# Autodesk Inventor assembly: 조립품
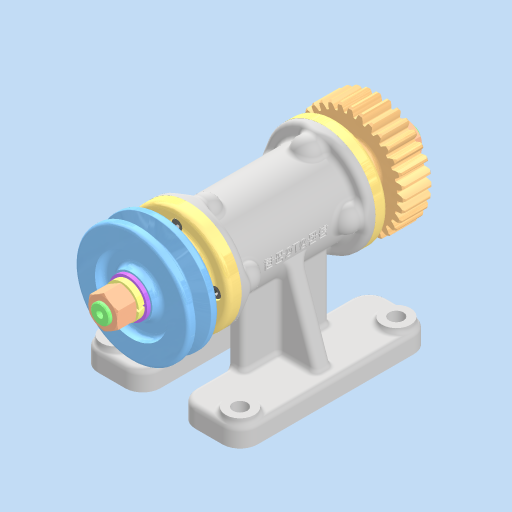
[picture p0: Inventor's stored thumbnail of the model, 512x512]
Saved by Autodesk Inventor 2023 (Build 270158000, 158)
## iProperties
Created: 2026-06
Part Number: 조립품
Document SubType Name: Assembly
Designer: home
Author: home
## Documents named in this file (18)
- C:\Users\home\Desktop\760603V1009\조립품.iam
- C:\Users\home\Desktop\760603V1009\부품.ipt
- C:\Users\home\Desktop\760603V1009\커버.ipt
- C:\Users\home\Desktop\760603V1009\6각 구멍붙이 볼트 M4x8.ipt
- C:\Users\home\Desktop\760603V1009\부품_MIR.ipt
- C:\Users\home\Desktop\760603V1009\커버_MIR.ipt
- C:\Users\home\Desktop\760603V1009\6각 구멍붙이 볼트 M4x8_MIR.ipt
- C:\Users\home\Desktop\760603V1009\깊은 홈 볼 베어링 6904.ipt
- C:\Users\home\Desktop\760603V1009\깊은 홈 볼 베어링 6904_MIR.ipt
- C:\Users\home\Desktop\760603V1009\축.ipt
- C:\Users\home\Desktop\760603V1009\오일 실 20 35 8.ipt
- C:\Users\home\Desktop\760603V1009\오일 실 20 35 8_MIR.ipt
- C:\Users\home\Desktop\760603V1009\V 벨트 풀리.ipt
- C:\Users\home\Desktop\760603V1009\평행 키 4x4x14.ipt
- C:\Users\home\Desktop\760603V1009\평 와셔 M12.ipt
- C:\Users\home\Desktop\760603V1009\스프링 와셔 M12.ipt
- C:\Users\home\Desktop\760603V1009\6각 너트 M12x1.ipt
- C:\Users\home\Desktop\760603V1009\스퍼 기어.ipt
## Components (11 placed, 4 different names)
1. 6각 구멍붙이 볼트 M4x8_MIR:1
2. 6각 구멍붙이 볼트 M4x8_MIR:2
3. 6각 구멍붙이 볼트 M4x8_MIR:3
4. 6각 구멍붙이 볼트 M4x8_MIR:4
5. V 벨트 풀리:1 — 각도:2
6. 6각 너트 M12x1:1
7. 6각 너트 M12x1:2
8. 6각 구멍붙이 볼트 M4x8:1
9. 6각 구멍붙이 볼트 M4x8:2
10. 6각 구멍붙이 볼트 M4x8:3
11. 6각 구멍붙이 볼트 M4x8:4
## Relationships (1: Angle 1)
- 각도:2 [Angle]: V 벨트 풀리:1
